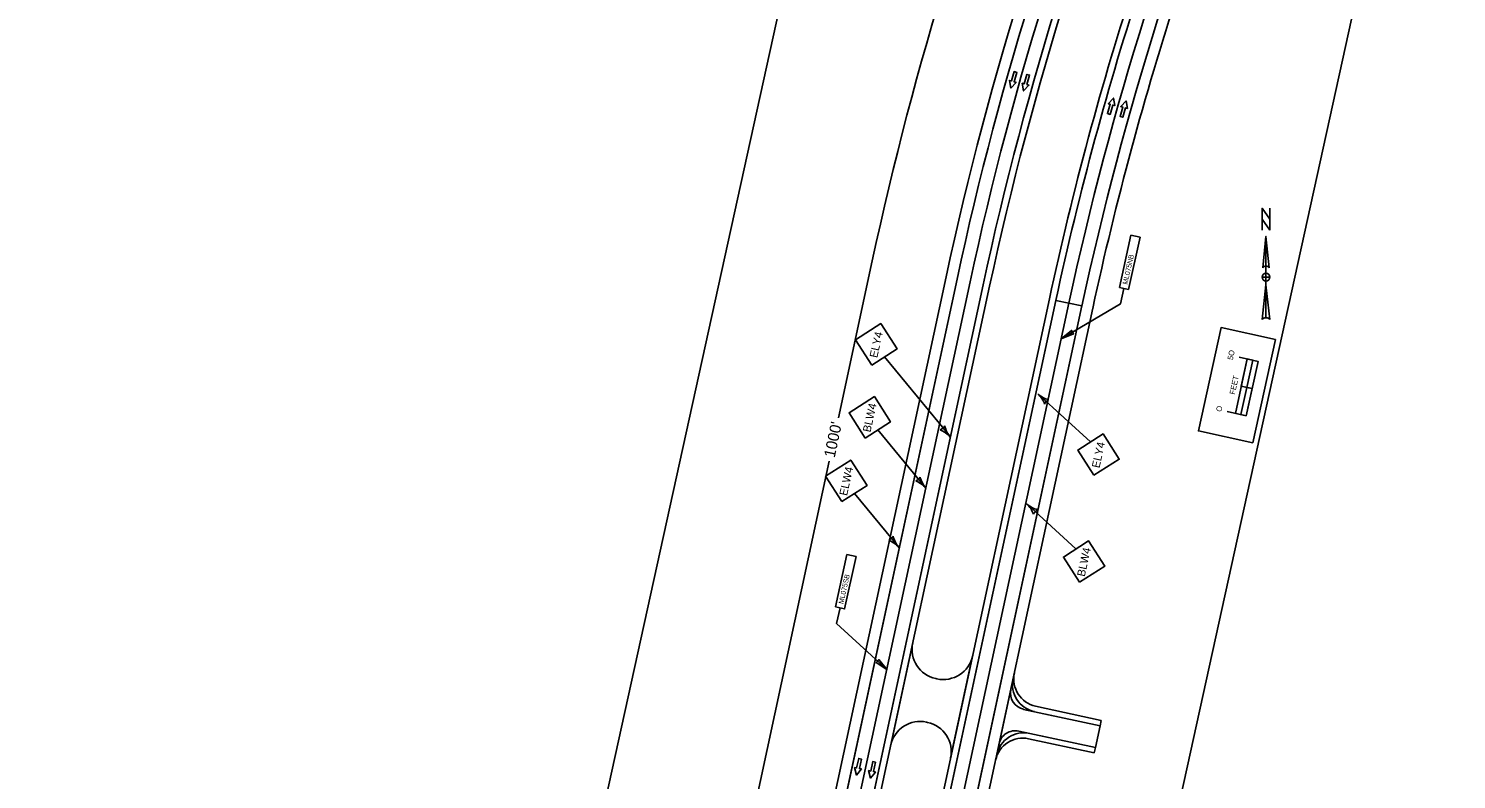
# Model space of a CAD drawing. Extents: x 14104283 to 14120882, y 8635219 to 8671666.
# Drawn here: x 14108141 to 14109426, y 8644454 to 8645129 of the extents above; entities that cross this region are included whole.
import ezdxf

# ---------------------------------------------------------------- set-up
doc = ezdxf.new("R2010")
doc.units = 0
for name, color, linetype in [('Cell', 7, 'Continuous'), ('dsnCellsNorthArrow', 7, 'Continuous'), ('dsnCellsScaleBlock', 7, 'Continuous'), ('dsnNonPlotable', 7, 'Continuous'), ('dsnPaintExistingEdgeLineRightWhite', 7, 'Continuous'), ('dsnPaintPlaceBrokenLineWhite', 7, 'Continuous'), ('dsnPaintPlaceEdgeLineLeftYellow', 7, 'Continuous'), ('dsnPaintPlaceEdgeLineRightWhite', 7, 'Continuous'), ('dsnPaintRemoveDoubleCenterLineYellow', 7, 'Continuous'), ('dsnShadingPaved', 7, 'Continuous'), ('dsnStdLabel', 7, 'Continuous'), ('dsnStgShadingPrevPav', 7, 'Continuous'), ('Text', 7, 'Continuous')]:
    doc.layers.add(name, color=color, linetype=linetype)

msp = doc.modelspace()

# ---------------------------------------------------------------- linework, layer by layer
at = {"layer": 'Cell'}
for points in [[(14109027.8, 8645090.4), (14109030.2, 8645089.7), (14109027.7, 8645081.3), (14109029.5, 8645080.7), (14109024.8, 8645075.6), (14109023.5, 8645082.5), (14109025.3, 8645082)], [(14109039.2, 8645087.9), (14109041.6, 8645087.2), (14109039.2, 8645078.8), (14109041, 8645078.2), (14109036.2, 8645073.1), (14109035, 8645080), (14109036.8, 8645079.5)], [(14109114.1, 8645051.9), (14109111.7, 8645052.6), (14109114.2, 8645061), (14109112.4, 8645061.5), (14109117.1, 8645066.6), (14109118.3, 8645059.8), (14109116.5, 8645060.3)], [(14109125.4, 8645049.4), (14109123, 8645050.1), (14109125.5, 8645058.5), (14109123.7, 8645059), (14109128.4, 8645064.1), (14109129.7, 8645057.3), (14109127.9, 8645057.8)], [(14108887.8, 8644472.9), (14108890.2, 8644472.3), (14108888.4, 8644463.8), (14108890.2, 8644463.4), (14108885.8, 8644457.9), (14108884.1, 8644464.7), (14108885.9, 8644464.3)], [(14108900.4, 8644470.1), (14108902.9, 8644469.5), (14108901, 8644461), (14108902.8, 8644460.6), (14108898.4, 8644455.2), (14108896.7, 8644461.9), (14108898.6, 8644461.5)]]:
    msp.add_lwpolyline(points, close=True, dxfattribs=at)
for points in [[(14109025.3, 8645082), (14109023.5, 8645082.5), (14109024.8, 8645075.6), (14109029.5, 8645080.7), (14109027.7, 8645081.3), (14109030.2, 8645089.7), (14109027.8, 8645090.4), (14109025.3, 8645082)], [(14109036.8, 8645079.5), (14109035, 8645080), (14109036.2, 8645073.1), (14109041, 8645078.2), (14109039.2, 8645078.8), (14109041.6, 8645087.2), (14109039.2, 8645087.9), (14109036.8, 8645079.5)], [(14109116.5, 8645060.3), (14109118.3, 8645059.8), (14109117.1, 8645066.6), (14109112.4, 8645061.5), (14109114.2, 8645061), (14109111.7, 8645052.6), (14109114.1, 8645051.9), (14109116.5, 8645060.3)], [(14109127.9, 8645057.8), (14109129.7, 8645057.3), (14109128.4, 8645064.1), (14109123.7, 8645059), (14109125.5, 8645058.5), (14109123, 8645050.1), (14109125.4, 8645049.4), (14109127.9, 8645057.8)], [(14108885.9, 8644464.3), (14108884.1, 8644464.7), (14108885.8, 8644457.9), (14108890.2, 8644463.4), (14108888.4, 8644463.8), (14108890.2, 8644472.3), (14108887.8, 8644472.9), (14108885.9, 8644464.3)], [(14108898.6, 8644461.5), (14108896.7, 8644461.9), (14108898.4, 8644455.2), (14108902.8, 8644460.6), (14108901, 8644461), (14108902.9, 8644469.5), (14108900.4, 8644470.1), (14108898.6, 8644461.5)]]:
    msp.add_lwpolyline(points, dxfattribs=at)
at = {"layer": 'dsnCellsNorthArrow'}
for p, q in [((14109254.3, 8644942.2), (14109257.1, 8644914.1)), ((14109254.3, 8644942.2), (14109254.3, 8644869)), ((14109251.5, 8644914.1), (14109251.5, 8644914.1)), ((14109251.6, 8644914.3), (14109252.1, 8644914.9)), ((14109250.8, 8644867.6), (14109254.3, 8644898.6)), ((14109254.3, 8644902.1), (14109254.3, 8644902.1))]:
    msp.add_line(p, q, dxfattribs=at)
msp.add_lwpolyline([(14109257.8, 8644947.9), (14109250.8, 8644957.7), (14109250.8, 8644967.6), (14109257.8, 8644957.7)], close=True, dxfattribs=at)
for points in [[(14109250.8, 8644947.9), (14109250.8, 8644967.6), (14109257.8, 8644957.7), (14109257.8, 8644967.6)], [(14109251.5, 8644914.1), (14109254.3, 8644942.2), (14109254.3, 8644915.5)], [(14109254.3, 8644902.1), (14109254.3, 8644905.6), (14109250.8, 8644905.6)], [(14109257.8, 8644905.6), (14109254.3, 8644905.6), (14109254.3, 8644909.1)], [(14109254.3, 8644869), (14109254.3, 8644898.6), (14109257.8, 8644867.6)]]:
    msp.add_lwpolyline(points, dxfattribs=at)
for centre, radius, start, end in [((14109254.3, 8644905.6), 3.52, 90, 180), ((14109254.3, 8644905.6), 3.52, 180, 270), ((14109254.3, 8644912), 3.52, 90.0204, 143.1257), ((14109254.3, 8644912), 3.52, 36.8481, 90.0218), ((14109254.3, 8644905.6), 3.52, 0, 90), ((14109254.3, 8644905.6), 3.52, 270, 360), ((14109254.3, 8644863.9), 5.1, 89.9894, 133.619), ((14109254.3, 8644863.9), 5.11, 46.4021, 90.0006)]:
    msp.add_arc(centre, radius, start, end, dxfattribs=at)
at = {"layer": 'dsnCellsScaleBlock'}
msp.add_line((14109241.9, 8644805.4), (14109232.1, 8644807.6), dxfattribs=at)
msp.add_line((14109241.9, 8644805.4), (14109232.1, 8644807.6), dxfattribs=at)
for points in [[(14109242.5, 8644756.7), (14109193.6, 8644767.4), (14109214, 8644860.2), (14109262.8, 8644849.4)], [(14109193.6, 8644767.4), (14109214, 8644860.2), (14109262.8, 8644849.4), (14109242.5, 8644756.7)], [(14109242.5, 8644756.7), (14109193.6, 8644767.4), (14109214, 8644860.2), (14109262.8, 8644849.4)], [(14109237, 8644806.5), (14109242.4, 8644830.9), (14109237.5, 8644832), (14109232.1, 8644807.6)], [(14109236.5, 8644781), (14109241.9, 8644805.4), (14109237, 8644806.5), (14109231.6, 8644782.1)]]:
    msp.add_lwpolyline(points, close=True, dxfattribs=at)
for points in [[(14109219.4, 8644784.8), (14109236.5, 8644781), (14109247.3, 8644829.8), (14109230.2, 8644833.6)], [(14109226.8, 8644783.1), (14109237.5, 8644832)]]:
    msp.add_lwpolyline(points, dxfattribs=at)
at = {"layer": 'dsnNonPlotable'}
msp.add_lwpolyline([(14108596.1, 8644144.9), (14108932.5, 8645675.8), (14109425.7, 8645567.5), (14109089.3, 8644036.5)], close=True, dxfattribs=at)
at = {"layer": 'dsnPaintExistingEdgeLineRightWhite'}
msp.add_line((14108724, 8643185.8), (14109088.7, 8644879.7), dxfattribs=at)
msp.add_arc((14111877.8, 8644279.1), 2853, 157.1547, 167.8488, dxfattribs=at)
at = {"layer": 'dsnPaintPlaceBrokenLineWhite'}
msp.add_line((14108623.3, 8643207.7), (14108988, 8644901.3), dxfattribs=at)
msp.add_lwpolyline([(14108306.4, 8641340.7), (14108389, 8641717), (14108712.3, 8643188.3), (14108894.6, 8644035.3), (14109077, 8644882.2)], dxfattribs=at)
for radius in [2956, 2865]:
    msp.add_arc((14111877.8, 8644279.1), radius, 157.1547, 167.8488, dxfattribs=at)
at = {"layer": 'dsnPaintPlaceEdgeLineLeftYellow'}
msp.add_line((14108700.5, 8643190.8), (14109065.3, 8644884.7), dxfattribs=at)
msp.add_lwpolyline([(14108999.8, 8644898.8), (14108635.1, 8643205.1), (14108434.9, 8642294.1)], dxfattribs=at)
for radius, start in [(2944, 157.1547), (2877, 161.903)]:
    msp.add_arc((14111877.8, 8644279.1), radius, start, 167.8488, dxfattribs=at)
at = {"layer": 'dsnPaintPlaceEdgeLineRightWhite'}
msp.add_lwpolyline([(14108976.3, 8644903.9), (14108611.6, 8643210.2), (14108202.1, 8641346.1)], dxfattribs=at)
msp.add_arc((14111877.8, 8644279.1), 2968, 157.1547, 167.8488, dxfattribs=at)
at = {"layer": 'dsnPaintRemoveDoubleCenterLineYellow'}
msp.add_lwpolyline([(14108306.4, 8641340.7), (14108389, 8641717), (14108712.3, 8643188.3), (14108894.6, 8644035.3), (14109077, 8644882.2)], dxfattribs=at)
msp.add_arc((14111877.8, 8644279.1), 2865, 157.1547, 167.8488, dxfattribs=at)
at = {"layer": 'dsnShadingPaved'}
msp.add_line((14109088.7, 8644879.7), (14109065.3, 8644884.7), dxfattribs=at)
for points in [[(14108976.3, 8644903.9), (14108611.6, 8643210.2), (14108202.1, 8641346.1)], [(14108434.9, 8642294.1), (14108635.1, 8643205.1), (14108999.8, 8644898.8)]]:
    msp.add_lwpolyline(points, dxfattribs=at)
msp.add_lwpolyline([(14109065.3, 8644884.7), (14109088.7, 8644879.7), (14108724, 8643185.7), (14108700.5, 8643190.9)], close=True, dxfattribs=at)
for radius, start in [(2968, 157.1547), (2944, 157.1547), (2853, 157.1547), (2877, 161.903)]:
    msp.add_arc((14111877.8, 8644279.1), radius, start, 167.8488, dxfattribs=at)
at = {"layer": 'dsnStdLabel'}
for p, q in [((14108900, 8644920.3), (14108869.6, 8644779.2)), ((14108910.9, 8644833.8), (14108970.3, 8644761.9)), ((14109096.3, 8644757.4), (14109048.9, 8644800.7)), ((14108905, 8644768.2), (14108948.2, 8644715.9)), ((14108861.2, 8644740.1), (14108659.4, 8643802.5)), ((14108883.9, 8644711.1), (14108923.9, 8644662.7)), ((14109083.3, 8644661.2), (14109039, 8644701.7))]:
    msp.add_line(p, q, dxfattribs=at)
for points in [[(14108899.5, 8644826.5), (14108922.3, 8644841.1), (14108907.7, 8644863.8), (14108885, 8644849.3)], [(14108893.7, 8644760.9), (14108916.4, 8644775.5), (14108901.9, 8644798.2), (14108879.1, 8644783.7)], [(14109099.5, 8644727.4), (14109122.3, 8644741.9), (14109107.7, 8644764.7), (14109085, 8644750.1)], [(14108872.5, 8644703.8), (14108895.3, 8644718.4), (14108880.7, 8644741.1), (14108858, 8644726.6)], [(14109086.5, 8644631.2), (14109109.3, 8644645.7), (14109094.7, 8644668.5), (14109072, 8644653.9)]]:
    msp.add_lwpolyline(points, close=True, dxfattribs=at)
for centre, radius, start, end in [((14111877.8, 8644279.1), 3046, 157.7272, 167.8488), ((14109033.5, 8644783.8), 22.9, 19.4977, 47.569), ((14109064.4, 8644817.6), 22.9, 227.5689, 255.6401), ((14109063.1, 8644787.7), 8.86, 119.8347, 155.3031), ((14108957.8, 8644776.5), 8.86, 292.8385, 328.307), ((14108952.8, 8644746.9), 22.9, 40.5727, 68.6439), ((14108987.7, 8644776.8), 22.9, 192.5015, 220.5728), ((14108935.7, 8644730.5), 8.86, 292.8385, 328.307), ((14108965.6, 8644730.8), 22.9, 192.5015, 220.5728), ((14108930.8, 8644701), 22.9, 40.5727, 68.6439), ((14109023.5, 8644684.8), 22.9, 19.4977, 47.569), ((14109054.5, 8644718.7), 22.9, 227.5689, 255.6401), ((14109053.2, 8644688.7), 8.86, 119.8347, 155.3031), ((14108911.4, 8644677.3), 8.86, 292.8385, 328.307), ((14108941.3, 8644677.6), 22.9, 192.5015, 220.5728), ((14108906.5, 8644647.7), 22.9, 40.5727, 68.6439)]:
    msp.add_arc(centre, radius, start, end, dxfattribs=at)
at = {"layer": 'dsnStgShadingPrevPav'}
for p, q in [((14108601.8, 8643212.3), (14108966.5, 8644906)), ((14108976.3, 8644903.9), (14108611.6, 8643210.2)), ((14109059.4, 8644886), (14108694.7, 8643192.1)), ((14108733.8, 8643183.6), (14109098.5, 8644877.6)), ((14108936.5, 8644576.7), (14108916.8, 8644484.8)), ((14108970.5, 8644473.3), (14108990.3, 8644565.1)), ((14108958.2, 8644544.4), (14108957.2, 8644544.6)), ((14109026.8, 8644544.6), (14109024.7, 8644534.9)), ((14109027.9, 8644549.5), (14109026.8, 8644544.6)), ((14109024.7, 8644534.9), (14109014.2, 8644486)), ((14109106.1, 8644507.1), (14109047, 8644519.8)), ((14108948.8, 8644505.5), (14108949.8, 8644505.3)), ((14109105.1, 8644502.2), (14109036.2, 8644517)), ((14109036.2, 8644517), (14109046, 8644514.9)), ((14109046, 8644514.9), (14109105.1, 8644502.2)), ((14109105.1, 8644502.2), (14109106.1, 8644507.1)), ((14109032, 8644497.5), (14109100.8, 8644482.7)), ((14109041.8, 8644495.4), (14109032, 8644497.5)), ((14109100.8, 8644482.7), (14109041.8, 8644495.4)), ((14109100.8, 8644482.7), (14109105.1, 8644502.2)), ((14109014.2, 8644486), (14109012.1, 8644476.2)), ((14109040.7, 8644490.5), (14109099.8, 8644477.8)), ((14109099.8, 8644477.8), (14109100.8, 8644482.7)), ((14109012.1, 8644476.2), (14109011, 8644471.3))]:
    msp.add_line(p, q, dxfattribs=at)
for points in [[(14108202.1, 8641346.1), (14108611.6, 8643210.2), (14108976.3, 8644903.9)], [(14108999.8, 8644898.8), (14108817.4, 8644052), (14108635.1, 8643205.1), (14108387.9, 8642080.1), (14108140.8, 8640955.1)], [(14108146.7, 8640953.8), (14108640.9, 8643203.9), (14109005.6, 8644897.6)], [(14108999.8, 8644898.8), (14108635.1, 8643205.1), (14108225.5, 8641340.9)]]:
    msp.add_lwpolyline(points, dxfattribs=at)
for centre, radius, start, end in [((14111877.8, 8644279.1), 2978, 157.1547, 167.8488), ((14111877.8, 8644279.1), 2968, 157.1547, 167.8488), ((14111877.8, 8644279.1), 2968, 157.1547, 167.8488), ((14111877.8, 8644279.1), 2944, 157.1547, 167.8488), ((14111877.8, 8644279.1), 2944, 157.1547, 167.8488), ((14111877.8, 8644279.1), 2938, 157.1547, 167.8488), ((14111877.8, 8644279.1), 2883, 161.9025, 167.8488), ((14111877.8, 8644279.1), 2843, 161.9025, 167.8488), ((14108962.9, 8644571), 27, 167.8488, 257.8488), ((14108963.9, 8644570.8), 27, 257.8488, 347.8488), ((14109051.2, 8644539.4), 25, 167.8488, 257.8481), ((14109051.2, 8644539.4), 25, 167.8488, 257.8481), ((14109052.3, 8644544.3), 25, 167.8488, 257.8488), ((14109039.4, 8644531.7), 15, 167.8488, 257.8488), ((14109039.4, 8644531.7), 15, 167.8488, 257.8488), ((14108943.1, 8644479.1), 27, 77.8488, 167.8488), ((14108944.1, 8644478.9), 27, 347.8488, 77.8488), ((14109036.5, 8644470.9), 25, 77.8488, 167.848), ((14109036.5, 8644470.9), 25, 77.8488, 167.848), ((14109028.8, 8644482.8), 15, 77.8488, 167.8488), ((14109028.8, 8644482.8), 15, 77.8488, 167.8488), ((14109035.5, 8644466.1), 25, 77.8488, 167.8488)]:
    msp.add_arc(centre, radius, start, end, dxfattribs=at)
at = {"layer": 'Text'}
for points in [[(14109122.4, 8644896.3), (14109132.8, 8644943.3), (14109141, 8644941.5), (14109130.6, 8644894.5)], [(14109122.4, 8644896.3), (14109132.8, 8644943.3), (14109141, 8644941.5), (14109130.6, 8644894.5)], [(14109070.1, 8644850.2), (14109079.4, 8644857.7), (14109081.2, 8644854.7)], [(14108866.9, 8644609.1), (14108877.2, 8644656.1), (14108885.4, 8644654.3), (14108875.1, 8644607.3)], [(14108866.9, 8644609.1), (14108877.2, 8644656.1), (14108885.4, 8644654.3), (14108875.1, 8644607.3)], [(14108913.4, 8644552.5), (14108903.5, 8644559.2), (14108905.9, 8644561.8)]]:
    msp.add_lwpolyline(points, close=True, dxfattribs=at)
for points in [[(14109126.5, 8644895.4), (14109123.4, 8644881.5), (14109070.1, 8644850.2)], [(14108871, 8644608.2), (14108867.8, 8644594.3), (14108913.4, 8644552.5)]]:
    msp.add_lwpolyline(points, dxfattribs=at)

# ---------------------------------------------------------------- texts
at = {"layer": 'dsnCellsScaleBlock'}
for s, p in [('5O', (14109224.4, 8644830.7)), ('FEET', (14109226.3, 8644799.7)), ('O', (14109214.2, 8644784.2))]:
    msp.add_text(s, height=5, rotation=77.6078, dxfattribs=at).set_placement(p)
at = {"layer": 'dsnStdLabel'}
for s, height, rotation, p in [('ELY4', 7.2, 77.6078, (14108904.5, 8644832.6)), ('BLW4', 7.2, 77.6078, (14108898.4, 8644765.7)), ("1000'", 10, 78.0531, (14108866.2, 8644742.7)), ('ELY4', 7.2, 77.6078, (14109104.5, 8644733.5)), ('ELW4', 7.2, 77.6078, (14108877.3, 8644708.6)), ('BLW4', 7.2, 77.6078, (14109091.2, 8644635.9))]:
    msp.add_text(s, height=height, rotation=rotation, dxfattribs=at).set_placement(p)
at = {"layer": 'Text'}
for s, p in [('ML075NB', (14109129.6, 8644898.6)), ('ML075SB', (14108874, 8644611.4))]:
    msp.add_text(s, height=4.48, rotation=77.6078, dxfattribs=at).set_placement(p)

doc.saveas('drawing.dxf')
